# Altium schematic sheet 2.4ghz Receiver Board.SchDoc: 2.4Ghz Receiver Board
size Letter
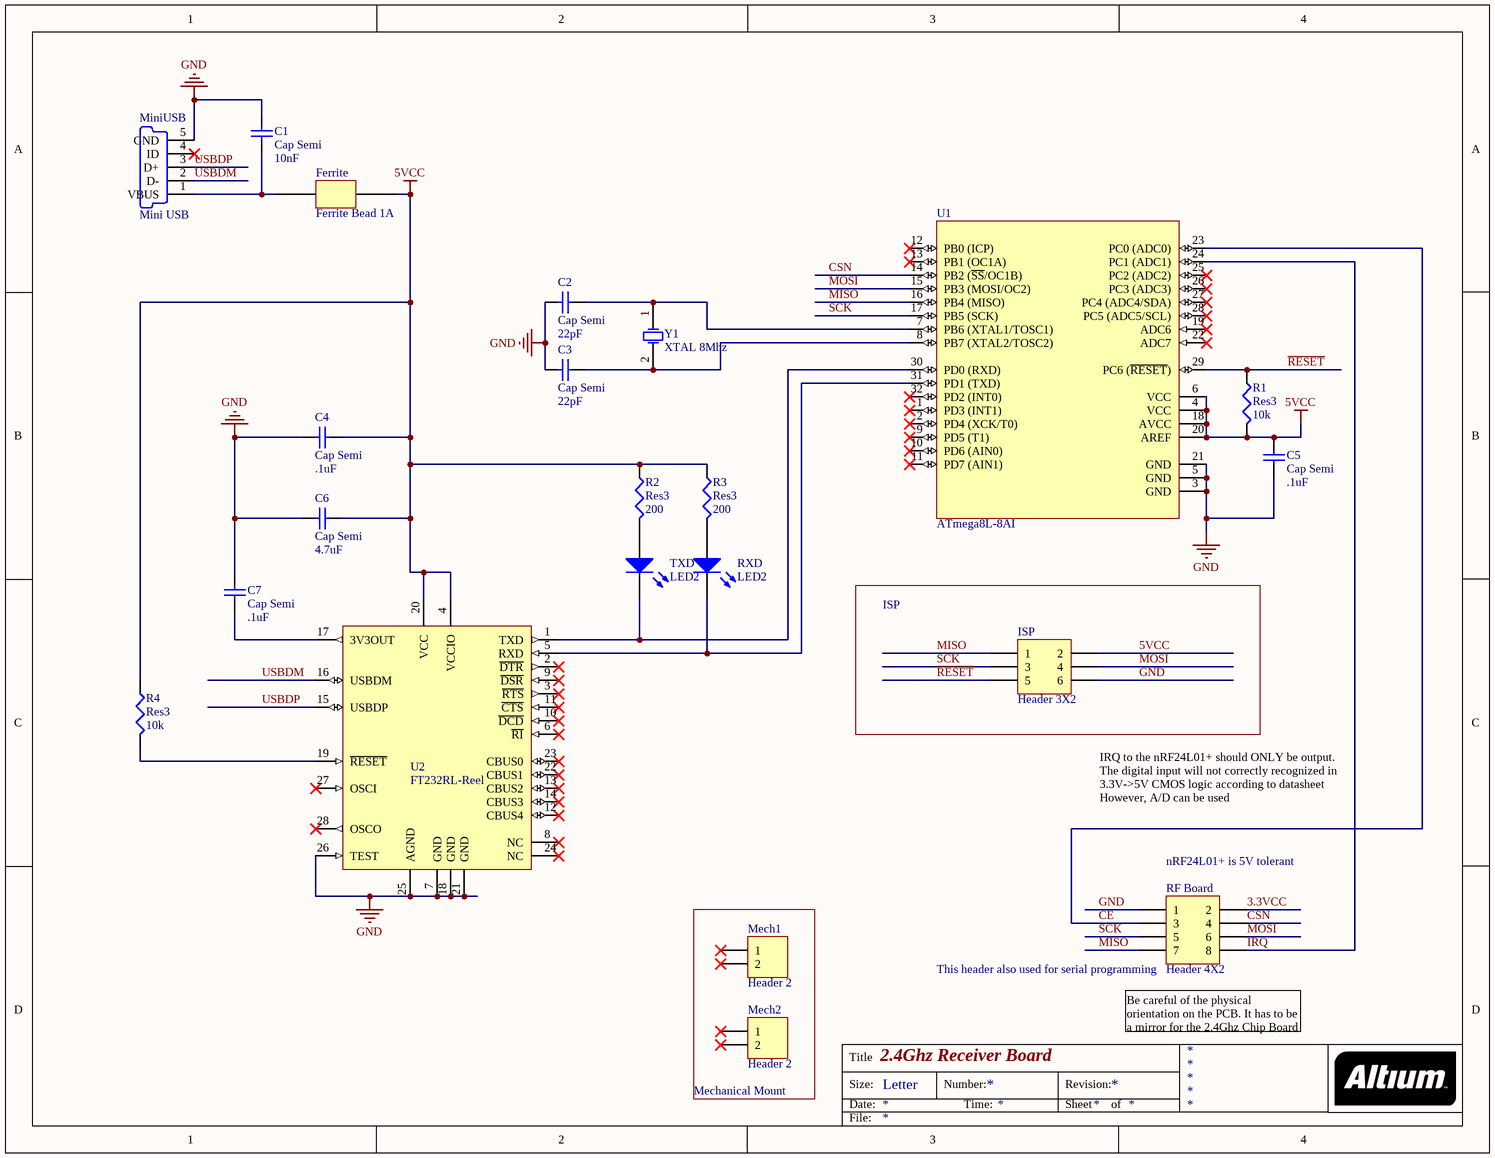
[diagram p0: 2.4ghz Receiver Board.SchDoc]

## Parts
C1  Cap Semi  value 10nF  [CAPC2012L]
C2  Cap Semi  value 22pF  [CAPC2012L]
C3  Cap Semi  value 22pF  [CAPC2012L]
C4  Cap Semi  value .1uF  [CAPC2012L]
C5  Cap Semi  value .1uF  [CAPC2012L]
C6  Cap Semi  value 4.7uF  [CAPC2012L]
C7  Cap Semi  value .1uF  [CAPC2012L]
Ferrite  Ferrite Bead 1A  [RESC2012N]
ISP  Header 3X2  [HDR2X3]
Mech1  Header 2  [HDR1X2]
Mech2  Header 2  [HDR1X2]
MiniUSB  Mini USB  [MINI USB]
R1  Res3  value 10k  [RESC2012N]
R2  Res3  value 200  [RESC2012N]
R3  Res3  value 200  [RESC2012N]
R4  Res3  value 10k  [RESC2012N]
RF_Board  Header 4X2  [HDR2X4]
RXD  LED2  [RESC3216N]
TXD  LED2  [RESC1608N]
U1  ATmega8L-8AI  [32A_N]
U2  FT232RL-Reel  [SSOP-28_N]
Y1  XTAL 8Mhz  [HC-49U - SMD]

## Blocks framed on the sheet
ISP: ISP
Mechanical Mount: Mech1 Mech2

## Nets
5VCC: C4.2 C5.2 C6.2 Ferrite.2 ISP.2 R1.2 R2.1 R3.1 R4.1 U1.4(VCC) U1.6(VCC) U1.18(AVCC) U1.20(AREF) U2.4(VCCIO) U2.20(VCC)
GND: C1.2 C2.1 C3.1 C4.1 C5.1 C6.1 C7.2 ISP.6 MiniUSB.5(GND) RF_Board.1 U1.3(GND) U1.5(GND) U1.21(GND) U2.7(GND) U2.18(GND) U2.21(GND) U2.25(AGND) U2.26(TEST)
3.3VCC: RF_Board.2
~{RESET}: ISP.5 R1.1 U1.29(PC6_(~{RESET}))
CE: RF_Board.3 U1.23(PC0_(ADC0))
CSN: RF_Board.4 U1.14(PB2_(~{SS}/OC1B))
IRQ: RF_Board.8 U1.24(PC1_(ADC1))
MISO: ISP.1 RF_Board.7 U1.16(PB4_(MISO))
MOSI: ISP.4 RF_Board.6 U1.15(PB3_(MOSI/OC2))
SCK: ISP.3 RF_Board.5 U1.17(PB5_(SCK))
USBDM: MiniUSB.2(D-) U2.16(USBDM)
USBDP: MiniUSB.3(D+) U2.15(USBDP)
NetC1_1: C1.1 Ferrite.1 MiniUSB.1(VBUS)
NetC2_2: C2.2 U1.7(PB6_(XTAL1/TOSC1)) Y1.1(OSC1)
NetC3_2: C3.2 U1.8(PB7_(XTAL2/TOSC2)) Y1.2(OSC2)
NetC7_1: C7.1 U2.17(3V3OUT)
NetR2_2: R2.2 TXD.1(A)
NetR3_2: R3.2 RXD.1(A)
NetR4_2: R4.2 U2.19(~{RESET})
NetRXD_2: RXD.2(K) U1.31(PD1_(TXD)) U2.5(RXD)
NetTXD_2: TXD.2(K) U1.30(PD0_(RXD)) U2.1(TXD)

Not connected (* = marked no-connect by the designer): Mech1 1* 2*; Mech2 1* 2*; MiniUSB 4(ID)*; U1 1(PD3_(INT1))* 2(PD4_(XCK/T0))* 9(PD5_(T1))* 10(PD6_(AIN0))* 11(PD7_(AIN1))* 12(PB0_(ICP))* 13(PB1_(OC1A))* 19(ADC6)* 22(ADC7)* 25(PC2_(ADC2))* 26(PC3_(ADC3))* 27(PC4_(ADC4/SDA))* 28(PC5_(ADC5/SCL))* 32(PD2_(INT0))*; U2 2(~{DTR})* 3(~{RTS})* 6(~{RI})* 8(NC)* 9(~{DSR})* 10(~{DCD})* 11(~{CTS})* 12(CBUS4)* 13(CBUS2)* 14(CBUS3)* 22(CBUS1)* 23(CBUS0)* 24(NC)* 27(OSCI)* 28(OSCO)*

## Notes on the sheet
- IRQ to the nRF24L01+ should ONLY be output. The digital input will not correctly recognized in 3.3V->5V CMOS logic according to datasheet
  However, A/D can be used
- (near RF_Board) nRF24L01+ is 5V tolerant
- (near RF_Board) This header also used for serial programming
- (near RF_Board) Be careful of the physical orientation on the PCB. It has to be a mirror for the 2.4Ghz Chip Board

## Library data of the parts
C1-C7 = Cap Semi: Capacitor (Semiconductor SIM Model)
Ferrite = Ferrite Bead
ISP = Header 3X2: Header, 3-Pin, Dual row
Mech1 Mech2 = Header 2: Header, 2-Pin
R1-R4 = Res3: Resistor
RF_Board = Header 4X2: Header, 4-Pin, Dual row
RXD TXD = LED2: Typical RED, GREEN, YELLOW, AMBER GaAs LED
U1 = ATmega8L-8AI: 8-Bit AVR Microcontroller with 8K Bytes of In-System Programmable Flash Memory
U2 = FT232RL-Reel: USB UART Asynchronous Serial Data Transfer Chip, SSOP-28, Tape and Reel
Y1 = XTAL: Crystal Oscillator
